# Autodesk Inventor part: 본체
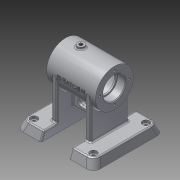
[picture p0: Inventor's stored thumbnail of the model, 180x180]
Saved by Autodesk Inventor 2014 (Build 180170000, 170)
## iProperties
Created: 2016-07
Part Number: 본체
Material: 알루미늄 6061
Document SubType Name: Modeling
Designer: basic
Density: 2.71 g/cm^3
Appearance: 알루미늄 - 평지
Mass: 473.747 g
Surface Area: 532.523 cm^2
Volume: 174.814 cm^3
Author: basic
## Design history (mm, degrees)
sketch "스케치12"
  geometry: L1 (35, 0)-(-35, 0); L2 (35, 0)-(35, 27); L3 (35, 27)-(-35, 27); L4 (-35, 27)-(-35, 0); L5 (35, 16)-(23, 16); L6 (23, 16)-(23, 14); L7 (23, 14)-(21, 14); L8 (21, 14)-(21, 22); L9 (21, 22)-(-21, 22); L10 (-21, 22)-(-21, 14); L11 (-21, 14)-(-23, 14); L12 (-23, 14)-(-23, 16); L13 (-23, 16)-(-35, 16); 2 further points
  constraints: 26 end point, 7 parallel, 5 perpendicular, 3 equal length, 2 point on line, 1 coincident, 1 horizontal, 1 midpoint
  dimensions: "d36" = 70 distance of L1.start L1.end; "d37" = 54 diameter of L3 L1; "d38" = 44 diameter of L9 L1; "d39" = 32 diameter of L5 L1; "d40" = 28 diameter of L7 L1; "d41" = 12 distance of L5.start L5.end; "d42" = 42 distance of L8.end L9.end; "d43" = 32 diameter of L13 L1
revolve "회전1" sketch "스케치12" stored, may be unused: angle "d44" = 90 deg
node "작업 평면3"
sketch "스케치13"
  geometry: L1 (-55, 50)-(55, 50); L2 (55, 50)-(55, -50); L3 (55, -50)-(-55, -50); L4 (-55, -50)-(-55, 50); L5 (-55, 50)-(55, -50); L6 (55, 50)-(-55, -50); 1 further point
  constraints: 12 end point, 2 midpoint, 2 parallel, 1 horizontal, 1 perpendicular
  dimensions: "d46" = 100 distance of L3.end L1.start; "d47" = 110 distance of L2.end L3.end
extrude "돌출7" join sketch "스케치13" distance "d48" = 12; taper "d49" = -20 deg
sketch "스케치14"
  geometry: L1 (55, 50)-(-55, 50) reference; L2 (-20, -50)-(20, -50); L3 (20, -50)-(20, 50); L4 (20, 50)-(-20, 50); L5 (-20, 50)-(-20, -50); L6 (-20, -50)-(20, 50); L7 (20, -50)-(-20, 50); 3 further points
  constraints: 12 end point, 2 midpoint, 2 parallel, 1 horizontal, 1 perpendicular, 1 point on line
  dimensions: "d52" = 40 distance of L3.end L4.end
extrude "돌출8" cut sketch "스케치14" stored distance "d53" = 10; taper "d54" = 0 deg
sketch "스케치15"
  geometry: L1 (20, 45.632)-(20, -45.632) reference; L2 (-20, 50)-(-20, -50) reference; L3 (55, -50)-(20, -50) reference; L4 (-55, -50)-(-55, 50) reference; L5 (-55, 50)-(-20, 50) reference; L6 (-20, -27)-(-28, -27); L7 (-28, -27)-(-28, 27); L8 (-28, 27)-(-20, 27); L9 (-20, 27)-(-20, -27); L10 (20, -27)-(28, -27); L11 (28, -27)-(28, 27); L12 (28, 27)-(20, 27); L13 (20, 27)-(20, -27); L14 (20, -50)-(20, 50) reference; L15 (20, 50)-(55, 50) reference; L16 (55, 50)-(55, -50) reference; L17 (-20, -50)-(-55, -50) reference; 5 further points
  constraints: 16 end point, 4 parallel, 2 horizontal, 2 horizontal alignment, 2 midpoint, 2 perpendicular, 2 point on line
  dimensions: "d55" = 54 distance of L8.end L6.start; "d56" = 8 distance of L6.start L6.end; "d57" = 54 distance of L12.end L10.start; "d58" = 8 distance of L10.start L10.end
extrude "돌출9" join sketch "스케치15" stored distance "d59" = 10; taper "d60" = 0 deg
sketch "스케치16"
  geometry: L1 (21, 22)-(-21, 22) reference; L2 (-21, 22)-(-21, 14) reference; L3 (-21, 14)-(-23, 14) reference; L4 (-23, 14)-(-23, 16) reference; L5 (-23, 16)-(-35, 16) reference; L6 (-35, 16)-(-35, 27) reference; L7 (-35, 27)-(35, 27) reference; L8 (35, 27)-(35, 16) reference; L9 (35, 16)-(23, 16) reference; L10 (23, 16)-(23, 14) reference; L11 (23, 14)-(21, 14) reference; L12 (21, 14)-(21, 22) reference; L13 (-21, -22)-(21, -22) reference; L14 (21, -22)-(21, -14) reference; L15 (21, -14)-(23, -14) reference; L16 (23, -14)-(23, -16) reference; L17 (23, -16)-(35, -16) reference; L18 (35, -16)-(35, -27) reference; L19 (35, -27)-(28, -27) reference; L20 (28, -27)-(28, -58) reference; L21 (28, -58)-(50.632, -58) reference; L22 (50.632, -58)-(55, -70) reference; L23 (55, -70)-(20, -70) reference; L24 (20, -70)-(20, -27) reference; L25 (20, -27)-(-20, -27) reference; L26 (-20, -27)-(-20, -70) reference; L27 (-20, -70)-(-55, -70) reference; L28 (-55, -70)-(-50.632, -58) reference; L29 (-50.632, -58)-(-28, -58) reference; L30 (-28, -58)-(-28, -27) reference; L31 (-28, -27)-(-35, -27) reference; L32 (-35, -27)-(-35, -16) reference; L33 (-35, -16)-(-23, -16) reference; L34 (-23, -16)-(-23, -14) reference; L35 (-23, -14)-(-21, -14) reference; L36 (-21, -14)-(-21, -22) reference; L37 (20, -48)-(-20, -48); 1 further point
  constraints: 2 end point, 2 point on line, 1 perpendicular
  dimensions: "d62" = 21 distance between parallel lines of L37 L25
feature "리브1" sketch "스케치16" dims "d63" = 1, "d64" = 8, "d65" = 0, "d66" = 0, "d67" = 1, "d68" = 1
sketch "스케치17"
  geometry: L1 (0, 0)-(40, 0) reference; L2 (12, -11.298)-(28, -11.298); L3 (12, -14.798)-(28, -14.798); L4 (28, -7.798)-(12, -7.798); L5 (40, -31.298)-(40, -43.298) reference; L6 (75, -43.298)-(40, -43.298) reference; L7 (-15, 53.702)-(-15, -0.298) reference; L8 (75, -43.298)-(70.632, -31.298) reference; L9 (0, -43.298)-(0, -31.298) reference; L10 (-35, -43.298)-(-30.632, -31.298) reference; L11 (0, -43.298)-(-35, -43.298) reference; L12 (70.632, -31.298)-(40, -31.298) reference; L13 (0, -31.298)-(-30.632, -31.298) reference; A1 r 3.5 centre (12, -11.298) between (12, -7.798) and (12, -14.798); A2 r 3.5 centre (28, -11.298) between (28, -14.798) and (28, -7.798); 2 further points
  constraints: 8 end point, 4 point on circle, 4 tangent, 2 centre point, 2 parallel, 1 midpoint
  dimensions: "d69" = 32 distance from line of L6 point (20, -11.298); "d70" = 35 distance from line of L7 point (20, -11.298); "d71" = 23 dimension on A2 A1; "d72" = 3.5 radius of A2
extrude "돌출10" cut sketch "스케치17" stored distance "d73" = 10; taper "d74" = 0 deg
fillet "모깎기6" dims "d75" = 2
sketch "스케치18"
  geometry: L1 (0, 0)-(-21, 0); C1 r 16 at (0, 0) reference; 1 further point
  constraints: 2 end point, 1 coincident, 1 horizontal
  dimensions: "d76" = 21 distance of L1.start L1.end
hole "구멍1" sketch "스케치18" at (-21, 0) diameter "d77" = 3.242; stored, may be unused: countersink angle "d81" = 90 deg, drill point angle "d83" = 118 deg; dims "d78" = 8, "d79" = 4, "d80" = 2, "d82" = 10
node "작업 평면5"
sketch "스케치20"
  geometry: L1 (35, -27)-(35, 27) reference; L2 (35, 0)-(13, 0); C1 r 5 at (13, 0); 1 further point
  constraints: 2 end point, 1 centre point, 1 coincident, 1 midpoint, 1 perpendicular
  dimensions: "d91" = 22 distance of L2.start L2.end; "d92" = 10 diameter of C1
extrude "돌출11" join sketch "스케치20" stored distance "d93" = 10; taper "d94" = 0 deg
sketch "스케치21"
  geometry: C1 r 5 at (0, 0) reference; 2 further points
  constraints: 1 coincident
hole "구멍2" sketch "스케치21" at (0, 0) diameter "d95" = 5.188; stored, may be unused: countersink angle "d99" = 90 deg, drill point angle "d101" = 118 deg; dims "d96" = 8, "d97" = 4, "d98" = 2, "d100" = 10
fillet "모깎기7" dims "d102" = 2
chamfer "모따기1" distance "d103" = 1; stored, may be unused: second distance "d104" = 2, angle "d105" = 45 deg
fillet "모깎기8" dims "d106" = 0.3
fillet "모깎기9" dims "d107" = 3
fillet "모깎기10" dims "d108" = 2
fillet "모깎기11" dims "d109" = 2
fillet "모깎기12" dims "d110" = 2
fillet "모깎기13" dims "d111" = 2
fillet "모깎기14" dims "d112" = 2
node "작업 평면7"
sketch "스케치23"
  geometry: L1 (35, 27)-(-35, 27) reference; L2 (-35, 27)-(-35, -27) reference; 2 further points
  constraints: 1 other
  dimensions: "d115" = 35 distance from line of L2 point (0, 0); "d116" = 27 distance from line of point (0, 0) L1
feature "엠보싱1" sketch "스케치23" dims "d36" = 70, "d37" = 54, "d38" = 44, "d39" = 32, "d40" = 28, "d41" = 12, "d42" = 42, "d43" = 32, "d46" = 100, "d47" = 110, "d117" = 0.5, "d118" = 0
fillet "모깎기16" dims "d120" = 2
fillet "모깎기17" dims "d121" = 2
fillet "모깎기18" dims "d122" = 10
sketch "스케치26"
  geometry: L1 (-41.714, 44.232)-(-22, 44.232) reference; L2 (0, 0)-(42.5, 0); L3 (42.5, 0)-(42.5, 37.5); 1 further point
  constraints: 4 end point, 1 coincident, 1 parallel, 1 perpendicular
  dimensions: "d123" = 42.5 distance of L2.start L2.end; "d124" = 37.5 distance of L2.end L3.end
hole "구멍3" sketch "스케치26" at (42.5, 37.5) diameter "d125" = 6; stored, may be unused: countersink angle "d129" = 90 deg, drill point angle "d131" = 118 deg; dims "d126" = 6, "d127" = 10, "d128" = 4, "d130" = 10
sketch "스케치27"
  geometry: L1 (4, -43.5)-(4, -46) reference; L2 (2, -48)-(-2, -48) reference; L3 (-4, -46)-(-4, -43.5) reference; L4 (-2, -41.5)-(2, -41.5) reference; L5 (2, -34.5)-(-2, -34.5) reference; L6 (-4, -32.5)-(-4, -28.373) reference; L7 (-26.928, 1.971)-(-27.429, 1.971) reference; L8 (-27.396, 2.385)-(-26.894, 2.385) reference; L9 (4, -28.373)-(4, -32.5) reference; L10 (0, 0)-(15.898, -25.441); L11 (15.898, -25.441)-(10.809, -28.621); L12 (10.809, -28.621)-(6.57, -21.837); L13 (11.658, -18.657)-(6.57, -21.837); C1 r 22 at (0, 0) reference; A1 r 2 centre (2, -43.5) between (4, -43.5) and (2, -41.5) reference; A2 r 2 centre (2, -46) between (2, -48) and (4, -46) reference; A3 r 2 centre (-2, -46) between (-4, -46) and (-2, -48) reference; A4 r 2 centre (-2, -43.5) between (-2, -41.5) and (-4, -43.5) reference; A5 r 2 centre (2, -32.5) between (2, -34.5) and (4, -32.5) reference; A6 r 2 centre (-2, -32.5) between (-4, -32.5) and (-2, -34.5) reference; A7 r 2 centre (-6, -28.373) between (-4, -28.373) and (-5.586, -26.416) reference; A8 r 27 centre (0, 0) between (-26.928, 1.971) and (-5.586, -26.416) reference; A9 r 27.5 centre (0, 0) between (-27.396, 2.385) and (-27.429, 1.971) reference; A10 r 27 centre (0, 0) between (5.586, -26.416) and (-26.894, 2.385) reference; A11 r 2 centre (6, -28.373) between (5.586, -26.416) and (4, -28.373) reference; 1 further point
  constraints: 8 end point, 3 perpendicular, 1 point on line, 1 tangent
  dimensions: "d132" = 32 deg angle of L10 L6; "d133" = 30 distance of L10.start L10.end; "d134" = 6 distance of L10.end L11.end
revolve "회전2" sketch "스케치27" stored, may be unused: angle "d135" = 90 deg
sketch "스케치28"
  geometry: C1 r 6 at (0, 0) reference; 1 further point
  constraints: 1 coincident
hole "구멍4" sketch "스케치28" at (0, 0) diameter "d136" = 5.188; stored, may be unused: countersink angle "d140" = 90 deg, drill point angle "d142" = 118 deg; dims "d137" = 20, "d138" = 10, "d139" = 4, "d141" = 10
fillet "모깎기19" dims "d143" = 2
node "솔리드4"
pattern_circular "원형 패턴1" dims angle "d85" = 360 deg
mirror "대칭1"
mirror "대칭2"
mirror "대칭3"
node "투영된 루프4"
node "투영된 루프5"
node "절단 모서리 투영1"
node "절단 모서리 투영2"
other parameters: "d61" = 21, "d114" = -27
